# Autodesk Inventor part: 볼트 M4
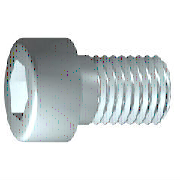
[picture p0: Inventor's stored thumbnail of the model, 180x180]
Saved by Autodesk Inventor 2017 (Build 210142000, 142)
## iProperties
IsCustomPart: 0
Created: 2009-02
Part Number: 볼트 M4
Material: 강철, 연강
Description: 6각머리 태핑 나사
Document SubType Name: Modeling
Standard: KS B 1003
Standards Organization: KS
Language: ko-KR
Size Designation: M 4 x 12
Categories: <MemberInstance><Categories><Category DisplayName="조임쇠" InternalName="e4da775c-781d-43d5-af7c-5136215cf5a6" Mnemonic="FSTN"><Category DisplayName="볼트" InternalN
Density: 1 g/cm^3
Appearance: 차가운 흰색
Author: pww
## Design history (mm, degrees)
sketch "스케치1"
  geometry: L1 (-1, 0)-(12, 0); L2 (12, 0)-(12, 2); L3 (12, 2)-(1.75, 2); L4 (1.75, 2)-(1.32, 2); L5 (1.32, 2)-(0, 2); L6 (0, 2)-(0, 3.5); L7 (0, 3.5)-(-4, 3.5); L8 (-4, 3.5)-(-4, 1.732); L9 (-4, 1.732)-(-2, 1.732); L10 (-2, 1.732)-(-1, 0); L11 (-7.2, 0)-(15.2, 0) reference; L12 (0, -0.7)-(0, 4.2) reference; L13 (1.75, 2)-(0, 2)
  constraints: 22 end point, 6 parallel, 2 collinear, 2 perpendicular, 1 horizontal, 1 point on line
  dimensions: "d1" = 10.25 distance from line of L3.end L2 (= GEL); "d2" = 0.42952 distance of L4.end L3.end (computed from GAL); "d3" = 4 distance between parallel lines of L8 L6 (= KOH); "d4" = 2 distance of L8.end L9.end (= INTI); "d5" = 60 deg angle of L10 L1; "d6" = 4 diameter of L3 L1 (= GD); "d7" = 4 diameter of L5 L1 (= BDM); "d8" = 3.4641 diameter of L9 L1 (= 1.1547 x SW); "d9" = 7 diameter of L7 L1 (= KOD); "d26" = 12 distance between parallel lines of L12 L2 (= NLG)
revolve "본체" sketch "스케치1" stored, may be unused: angle "d10" = 90 deg
sketch "스케치2"
  geometry: L1 (0, -4.9)-(0, 4.9) reference; L2 (-4.9, 0)-(4.9, 0) reference; L3 (1.732, 0)-(0.866, -1.5); L4 (0.866, -1.5)-(-0.866, -1.5); L5 (-0.866, -1.5)-(-1.732, 0); L6 (-1.732, 0)-(-0.866, 1.5); L7 (-0.866, 1.5)-(0.866, 1.5); L8 (0.866, 1.5)-(1.732, 0); 2 further points
  constraints: 12 end point, 1 coincident, 1 horizontal alignment, 1 point on line, 12 other
extrude "슬롯" join sketch "스케치2" stored distance "d11" = 10; taper "d12" = 0 deg
workplane "Work Plane1"
fillet "Fillet2" dims "d30" = 0.1 (= R)
body "Solid1"
fillet "모깎기1" dims "d17" = 0.4 (= RR)
feature "스레드" dims "d13" = 10.25 (= GEL), "d14" = 0
chamfer "모따기1" distance "d15" = 0.42941 (= -0.5 x SPD + 0.5 x GD); stored, may be unused: second distance "d16" = 0.42941 (= GUL), angle "d27" = 45 deg
other parameters: "GD" = 4 (= NND) [user parameter; used in 2 equation terms], "NLG" = 12 [user parameter; used in 1 equation term], "GEL" = 10.25 [user parameter; used in 2 equation terms], "KOD" = 7 [user parameter; used in 1 equation term], "KOH" = 4 [user parameter; used in 1 equation term], "INTI" = 2 [user parameter; used in 1 equation term], "GAL" = 0.42941 (= 0.61345 x PTC) [user parameter; used in 1 equation term], "GUL" = 0.42941 (= 0.61345 x PTC) [user parameter; used in 1 equation term], "BDM" = 4 (= NND) [user parameter; used in 1 equation term], "SW" = 3 [user parameter; used in 2 equation terms], "RR" = 0.4 [user parameter; used in 1 equation term], "SPD" = 3.14117 (= NND - 1.2269 x PTC) [user parameter; used in 1 equation term], "d19" = 0, "d28" = 0, "d29" = 0, "R" = 0.1 [user parameter; used in 1 equation term], "PHH" = 0.2 [user parameter], "GD1" = 3.14117 (= THREADDIA - 1.2269 x PTC) [user parameter], "THREADDIA" = 4 [user parameter; used in 1 equation term], "FAWI" = 45 deg [user parameter], "TPU" = 14.28571 (computed from PTC) [user parameter], "PTC" = 0.7 [user parameter; used in 5 equation terms], "NND" = 4 [user parameter; used in 3 equation terms], "TOA" = 30 deg [user parameter], "E0" = 3.465 (= 1.155 x SW) [user parameter]
